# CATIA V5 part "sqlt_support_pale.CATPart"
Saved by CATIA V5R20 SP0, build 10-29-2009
Part number: sqlt_support_pale
Publications: "Plan.1", "Point.1", "Droite.1", "Point.2", "Point.3", "Point.4", "Point.5", "Point.6", "Point.7", "Plan.2", "Point.8", "Fond du trou qui acceuille barre soutient", "diamètre_trou", "profondeur_trou"
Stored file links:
  D:\ecole\thinkmotion\sqlt_support_pale.CATPart
  D:\ecole\thinkmotion\sqlt_eolienne.CATProduct
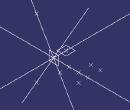
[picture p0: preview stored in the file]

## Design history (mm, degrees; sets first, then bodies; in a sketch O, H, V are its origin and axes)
Parameters
  `diamètre_trou` = 40 mm {= External.rayon_barre *2}
  profondeur_trou = 25 mm {= `External.profondeur_perçage`}
External parameters (linked from other documents)
  External.rayon_bati = 50 mm
  External.rayon_pivot = 30 mm
  External.hauteur_pivot = 40 mm
  External.hauteur_bati = 300 mm
  External.rayon_barre = 20 mm
  `External.profondeur_perçage` = 25 mm
Body1 (main body)
  Plane1: type Offset, RefPlane xy-plane, Offset 0
  Point1: (0, 0, 0)
  Line1 "Axe de rotation": type PtDir, RefPoint Point1, Direction yz-plane, Start 0, End 20
  Point2: (0, 80 {= External.rayon_bati +External.rayon_pivot}, 0)
  Point3: (0, 110 {= External.rayon_pivot +External.rayon_bati +30mm}, 0)
  Point4: (40 {= External.hauteur_pivot}, 80 {= External.rayon_bati +External.rayon_pivot}, 0)
  Point5: (40, 50 {= External.rayon_bati}, 0)
  Point6: (70 {= External.hauteur_pivot +30mm}, 50 {= External.rayon_bati}, 0), relative to Point1
  Point7: (70 {= External.hauteur_pivot +30mm}, 110 {= External.rayon_bati +External.rayon_pivot +30mm}, 0)
  Plane2 "Plan en contact avec bati": type Offset, RefPlane yz-plane, Offset 40 {= External.hauteur_pivot}
  Point8: (40 {= External.hauteur_pivot}, 110 {= External.rayon_bati +30mm+External.rayon_pivot}, 0)
  Plane3 "Fond du trou qui acceuille barre soutient": type Offset, RefPlane zx-plane, Offset 85 {= External.rayon_bati +External.rayon_pivot +30mm-profondeur_trou}
  Point9: type OnPlane, Support Plane2, H 0, V 0, Direction (0, 1, 0)
  Line2: type PtPt, FirstPoint Point9, SecondPoint Point8
  Plane4: type Angle, RefPlane Plane3, Direction Line1, Angle 120
  Line3: type Normal, RefPoint Point9, RefSkin Plane4, Start 0, End 20
  Point10: type OnCurve, Support Line3, Length 110 {= External.rayon_bati +External.rayon_pivot +30mm}
  Plane5: type Offset, RefPlane Plane4, Offset 85 {= External.rayon_bati +External.rayon_pivot +30mm-profondeur_trou}
  Plane6: type Angle, RefPlane Plane3, Direction Line1, Angle 240
  Line4: type Normal, RefPoint Point9, RefSkin Plane6, Start 0, End 20
  Point11: type OnCurve, Support Line4, Length 110 {= External.rayon_bati +External.rayon_pivot +30mm}
  Plane7: type Offset, RefPlane Plane6, Offset 85 {= External.rayon_pivot +External.rayon_bati +30mm-profondeur_trou}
